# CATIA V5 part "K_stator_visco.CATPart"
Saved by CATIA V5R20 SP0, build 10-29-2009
Part number: stator visco
Publications: "Face"
Bounding box of the stored display mesh (mm): x -169.989 to 169.989, y -364 to -145, z -169.989 to 169.989
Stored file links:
  G:\Khaled_CFAO_2011\ST2M\ST2M_GR1\mponsin\Khaled\CAD_ThinkMOTION\K_stator_visco.CATPart
  C:\Users\Socar\Documents\thinkmotion\Final\Diff2.CATProduct
  G:\Khaled_CFAO_2011\ST2M\ST2M_GR1\mponsin\Khaled\CAD_ThinkMOTION\K_mponsin.CATProduct
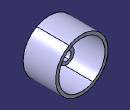
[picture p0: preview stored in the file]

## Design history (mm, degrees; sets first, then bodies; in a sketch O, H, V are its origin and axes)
External parameters (linked from other documents)
  `External.R cardan` = 30 mm
  `External.hauteur du visco` = 170 mm
  `External.R interface stat_tot` = 50 mm
Set1
  Plane1 "interface visco/embrayage": linked copy from another document
  DatumPoint1: linked copy from another document
  DatumPoint2: linked copy from another document
  Line1 "axe general": linked copy from another document
  Plane2 "stator_rotor2": linked copy from another document
  Plane3 "stator_rotor1": linked copy from another document
  Plane4 "stator_rotor3": linked copy from another document
Body1 (main body)
  Sketch1 on yz-plane, origin (0, 0, 0), H (0, 1, 0), V (0, 0, 1)
    line L1 (-360, 33) -> (-364, 33)
    point P2 (-364, 33)
    line L2 (-360, 33) -> (-360, 43)
    point P3 (-360, 43)
    line L3 (-360, 43) -> (-357, 43)
    line L4 (-357, 43) -> (-357, 170)
    line L5 (-357, 170) -> (-145, 170)
    line L6 (-145, 150) -> (-345, 150)
    line L7 (-345, 150) -> (-345, 50)
    line L8 (-345, 50) -> (-245, 50)
    line L9 (-245, 50) -> (-245, 30)
    line L10 (-245, 30) -> (-364, 30)
    line L11 (-364, 30) -> (-364, 33)
    reference projected point E1 (-364, 33) from vertex of DatumPoint1
    reference projected point E2 (-360, 43) from vertex of DatumPoint2
    reference projected line E3 through (0, 0) direction (1, 0) from Line1
    reference projected line E4 through (0, 0) direction (1, 0) from Line1
    reference intersected line E5 through (-245, 0) direction (0, 1) from Plane2
    reference intersected line E6 through (-345, 0) direction (0, 1) from Plane3
    reference projected line E7 through (0, 0) direction (1, 0) from Line1
    reference projected line E8 through (0, 0) direction (1, 0) from Line1
    line L12 (-145, 150) -> (-145, 170)
    distance L10 E3 = 30 {= `External.R cardan`}
    distance L5 E4 = 170 {= `External.hauteur du visco`}
    length L3 = 3
    distance L8 E7 = 50 {= `External.R interface stat_tot`}
    distance E8 L6 = 150
    length L6 = 200
    horizontal: L1 H, L3 H, L5 H, L6 H, L8 H, L10 H
    vertical: L2 V, L4 V, L7 V, L9 V, L11 V, L12 V
    coincidence: E1 P2, E2 P3, E5 L9, E6 L7
  Shaft1: profile Sketch1, axis Line1, angle 360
